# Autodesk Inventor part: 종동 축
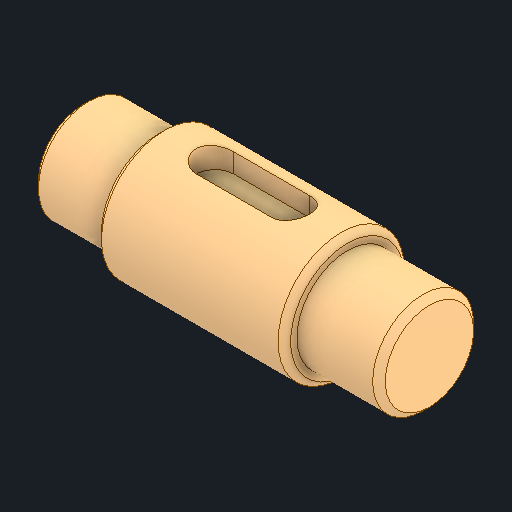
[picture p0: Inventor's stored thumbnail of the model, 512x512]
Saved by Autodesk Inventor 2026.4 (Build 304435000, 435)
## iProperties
Created: 2026-09
Part Number: 종동 축
Material: 강철, 탄소
Document SubType Name: Modeling
Designer: user
Density: 7.85 g/cm^3
Appearance: 기본값
Author: jhkim
Sending System: Autodesk Inventor 2027
Preprocessor: ST-DEVELOPER v20.1
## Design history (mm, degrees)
feature "솔리드1"
node "솔리드2"
